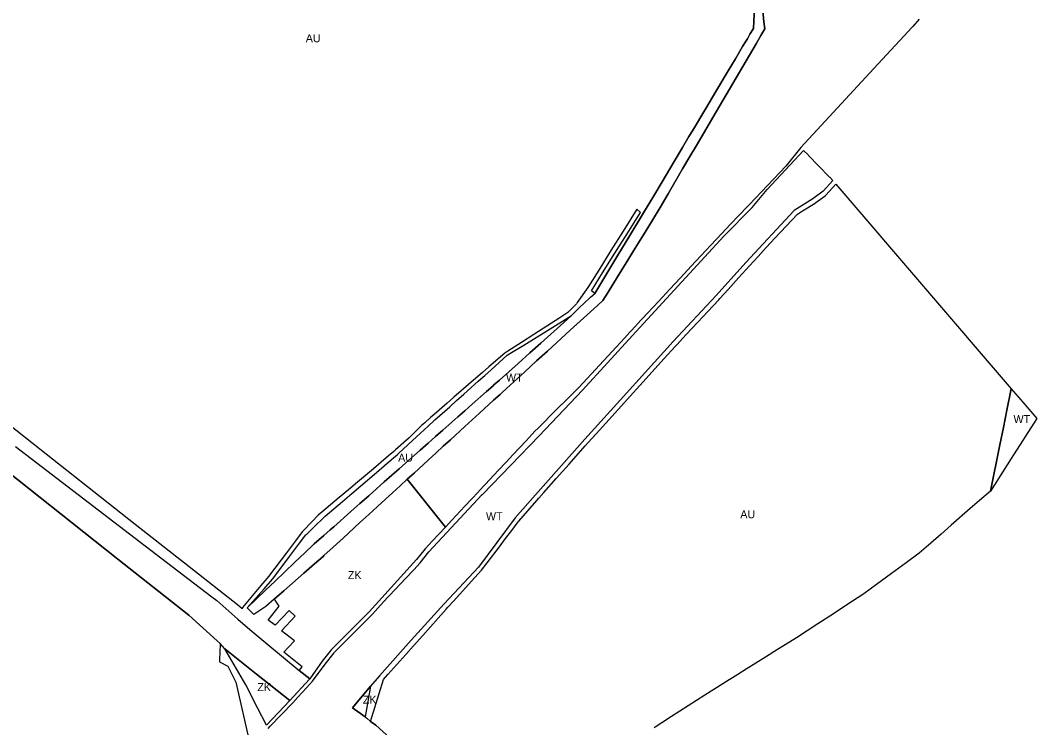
# Model space of a CAD drawing. Extents: x -537068 to -534056, y -1176840 to -1172401.
# Drawn here: x -534942 to -534307, y -1175088 to -1174646 of the extents above; entities that cross this region are included whole.
import ezdxf

# ---------------------------------------------------------------- set-up
doc = ezdxf.new("R2010")
doc.units = 0
for name, color, linetype in [('90640013', 7, 'Continuous'), ('90710013', 7, 'Continuous'), ('90750013', 7, 'Continuous')]:
    doc.layers.add(name, color=color, linetype=linetype)

msp = doc.modelspace()

# ---------------------------------------------------------------- linework, layer by layer
at = {"layer": '90640013'}
for points in [[(-534478.25, -1174635.29), (-534477.06, -1174647.13), (-534476.63, -1174651.47), (-534479.05, -1174655.6), (-534482.03, -1174660.69), (-534507.01, -1174703.32), (-534519.27, -1174724.24), (-534523.34, -1174731.19), (-534527.85, -1174738.88), (-534536.96, -1174754.44), (-534541.93, -1174762.92), (-534546.59, -1174770.87), (-534547.29, -1174772.07), (-534552.26, -1174780.1), (-534557.45, -1174788.49), (-534563.09, -1174797.6), (-534568.54, -1174806.41), (-534574.36, -1174815.82), (-534577.61, -1174821.08), (-534581.12, -1174824.28), (-534589.69, -1174832.1), (-534598.08, -1174839.75), (-534612.37, -1174852.78), (-534619.04, -1174858.87), (-534626.4, -1174865.59), (-534637.98, -1174876.15), (-534640.8, -1174878.72), (-534641.91, -1174879.74), (-534645.96, -1174883.45), (-534654.83, -1174891.57), (-534659.4, -1174895.76), (-534663.82, -1174899.8), (-534672.91, -1174908.12), (-534677.35, -1174912.19), (-534681.8, -1174916.26), (-534686.8, -1174920.84), (-534695.63, -1174928.92), (-534699.83, -1174932.76), (-534704.27, -1174936.83), (-534708.86, -1174941.03), (-534718.52, -1174949.88), (-534723.91, -1174954.82), (-534729.39, -1174959.83), (-534739.98, -1174969.53), (-534746.09, -1174975.13), (-534751.91, -1174980.46), (-534752.48, -1174980.98), (-534757.86, -1174985.68), (-534764.54, -1174991.52), (-534776.95, -1175002.38), (-534782.97, -1175007.65), (-534788.3, -1175012.3), (-534795.76, -1175017.23), (-534799.77, -1175013.15), (-534788.31, -1175002.15), (-534782.4, -1174996.48), (-534770.21, -1174984.78), (-534763.72, -1174978.55), (-534758.63, -1174973.67), (-534758, -1174973.12), (-534752.03, -1174967.91), (-534747.97, -1174964.37), (-534745.77, -1174962.42), (-534735.07, -1174952.95), (-534729.47, -1174947.99), (-534723.96, -1174943.11), (-534714.22, -1174934.48), (-534709.5, -1174930.3), (-534704.98, -1174926.3), (-534700.74, -1174922.54), (-534691.77, -1174914.6), (-534686.73, -1174910.14), (-534682.16, -1174906.09), (-534677.61, -1174902.06), (-534668.37, -1174893.88), (-534663.99, -1174890), (-534659.38, -1174885.92), (-534650.37, -1174877.94), (-534646.28, -1174874.32), (-534645.7, -1174873.81), (-534642.31, -1174870.78), (-534630.67, -1174860.39), (-534623.21, -1174853.72), (-534616.5, -1174847.72), (-534602.13, -1174834.89), (-534597.21, -1174830.49), (-534593.92, -1174827.17), (-534591.85, -1174825.08), (-534589.81, -1174823.19), (-534585.4, -1174819.11), (-534582.77, -1174816.67), (-534575.87, -1174805.3), (-534568.35, -1174792.9), (-534560.88, -1174780.59), (-534552.84, -1174767.33), (-534545.33, -1174754.73), (-534541.36, -1174748.06), (-534532.58, -1174733.33), (-534527.95, -1174725.55), (-534523.9, -1174718.75), (-534521.7, -1174715.06), (-534513.44, -1174701.2), (-534507.13, -1174690.61), (-534499.41, -1174677.64), (-534494.89, -1174670.06), (-534490.4, -1174662.53), (-534488.66, -1174659.61), (-534487.45, -1174657.59), (-534485.82, -1174654.85), (-534483.67, -1174651.23), (-534483.43, -1174646.62), (-534482.82, -1174635.13)], [(-534786.8, -1175088.49), (-534785.44, -1175087.07), (-534771.39, -1175072.42), (-534768.18, -1175068.9), (-534762.82, -1175063.03), (-534759.09, -1175058.95), (-534751.09, -1175048.36), (-534745.62, -1175041.13), (-534745.39, -1175040.83), (-534733.34, -1175028.8), (-534727.33, -1175022.8), (-534721.5, -1175016.99), (-534716.5, -1175011.48), (-534712.15, -1175006.68), (-534710.89, -1175005.34), (-534700.74, -1174994.57), (-534695.79, -1174989.31), (-534691.73, -1174984.99), (-534686.41, -1174978.09), (-534653.01, -1174942.33), (-534652.92, -1174942.24), (-534617.54, -1174905.69), (-534590.44, -1174877.09), (-534559.14, -1174842.98), (-534554.55, -1174837.98), (-534502.13, -1174780.9), (-534484.54, -1174763.09), (-534475.1, -1174751.76), (-534452.32, -1174727.32), (-534449.49, -1174730.22), (-534449.18, -1174730.55), (-534436.26, -1174743.82), (-534435.92, -1174744.17), (-534434.05, -1174746.09), (-534440.14, -1174752.91), (-534446.52, -1174757.52), (-534458.12, -1174764.98), (-534488.33, -1174797.34), (-534506.9, -1174817.91), (-534533.72, -1174846.67), (-534562.86, -1174878.98), (-534589.01, -1174907.71), (-534619.84, -1174942.57), (-534632.39, -1174956.93), (-534655.43, -1174987.67), (-534676.86, -1175010.7), (-534697.52, -1175033.38), (-534717.3, -1175055.5), (-534722.76, -1175062.11), (-534734.11, -1175075.61), (-534726.06, -1175081.25), (-534725.07, -1175082.09), (-534722.75, -1175084.04), (-534719.56, -1175086.43), (-534678.09, -1175123.81)], [(-534944.54, -1174912.26), (-534853.75, -1174981.84), (-534821.98, -1175006.14), (-534818.78, -1175008.59), (-534805.63, -1175020.1), (-534798.18, -1175026.62), (-534788.2, -1175034.87), (-534767.31, -1175052.15), (-534760.8, -1175057.54), (-534760.89, -1175057.67), (-534773.24, -1175070.91), (-534773.26, -1175070.93), (-534793.94, -1175054.45), (-534813.71, -1175038.69), (-534816.74, -1175035.44), (-534818.62, -1175033.74), (-534836.31, -1175017.73), (-534880.64, -1174982.65), (-534964.8, -1174916.06)]]:
    msp.add_lwpolyline(points, dxfattribs=at)
msp.add_lwpolyline([(-534335.66, -1174940.16), (-534329.75, -1174911.35), (-534327.52, -1174900.45), (-534325.32, -1174889.7), (-534322.58, -1174876.32), (-534315.41, -1174884.7), (-534306.74, -1174894.82), (-534322.65, -1174919.76)], close=True, dxfattribs=at)
at = {"layer": '90710013'}
for points in [[(-534760.8, -1175057.54), (-534767.31, -1175052.15), (-534765.58, -1175050.02), (-534776.91, -1175040.75), (-534774.24, -1175037.93), (-534770.39, -1175033.81), (-534778.49, -1175027.49), (-534769.81, -1175018.3), (-534773.59, -1175014.79), (-534782.29, -1175024), (-534786.84, -1175020.73), (-534779.83, -1175012.16), (-534782.3, -1175008.34), (-534782.97, -1175007.65), (-534776.95, -1175002.38), (-534764.54, -1174991.52), (-534757.86, -1174985.68), (-534752.48, -1174980.98), (-534751.91, -1174980.46), (-534746.09, -1174975.13), (-534739.98, -1174969.53), (-534729.39, -1174959.83), (-534723.91, -1174954.82), (-534718.52, -1174949.88), (-534708.86, -1174941.03), (-534704.27, -1174936.83), (-534699.83, -1174932.76), (-534676.03, -1174962.63), (-534680.11, -1174967.01), (-534684.1, -1174971.29), (-534688.65, -1174976.17), (-534694.19, -1174982.86), (-534723.62, -1175015.5), (-534747.13, -1175039.14), (-534752.93, -1175046.38)], [(-534773.26, -1175070.93), (-534787.72, -1175086.34), (-534787.86, -1175086.44), (-534793.42, -1175075.61), (-534800.74, -1175061.15), (-534813.71, -1175038.69), (-534793.94, -1175054.45)], [(-534726.06, -1175081.25), (-534734.11, -1175075.61), (-534722.76, -1175062.11)]]:
    msp.add_lwpolyline(points, close=True, dxfattribs=at)
at = {"layer": '90750013'}
for points in [[(-534482.82, -1174635.13), (-534483.43, -1174646.62), (-534483.67, -1174651.23), (-534485.82, -1174654.85), (-534487.45, -1174657.59), (-534488.66, -1174659.61), (-534490.4, -1174662.53), (-534494.89, -1174670.06), (-534499.41, -1174677.64), (-534507.13, -1174690.61), (-534513.44, -1174701.2), (-534521.7, -1174715.06), (-534523.9, -1174718.75), (-534527.95, -1174725.55), (-534532.58, -1174733.33), (-534541.36, -1174748.06), (-534545.33, -1174754.73), (-534552.84, -1174767.33), (-534560.88, -1174780.59), (-534568.35, -1174792.9), (-534575.87, -1174805.3), (-534582.77, -1174816.67), (-534584.75, -1174814.98), (-534577.84, -1174803.89), (-534570.19, -1174791.62), (-534562.58, -1174779.41), (-534554.28, -1174766.1), (-534556.56, -1174764.15), (-534565.02, -1174777.71), (-534572.63, -1174789.92), (-534580.26, -1174802.17), (-534587.03, -1174813.03), (-534593.65, -1174822.45), (-534594.13, -1174823.13), (-534595.88, -1174824.89), (-534599.49, -1174828.54), (-534604.65, -1174831.87), (-534620.87, -1174842.36), (-534628.44, -1174847.25), (-534636.95, -1174852.75), (-534638.95, -1174854.04), (-534648.87, -1174862.64), (-534652.89, -1174866.12), (-534656.99, -1174869.67), (-534666.1, -1174877.56), (-534670.72, -1174881.56), (-534674.99, -1174885.26), (-534681.63, -1174891.01), (-534684.36, -1174893.38), (-534685.1, -1174894.02), (-534688.97, -1174897.47), (-534690.89, -1174899.19), (-534693.48, -1174901.76), (-534698.23, -1174906.49), (-534698.64, -1174906.9), (-534707.2, -1174914.47), (-534708.32, -1174915.45), (-534711.49, -1174918.14), (-534716.11, -1174922.04), (-534721.01, -1174926.18), (-534730.87, -1174934.52), (-534736.54, -1174939.32), (-534742.3, -1174944.19), (-534753.14, -1174953.36), (-534755.41, -1174955.28), (-534759.21, -1174959.17), (-534764.81, -1174964.9), (-534765.49, -1174965.6), (-534769.74, -1174971.23), (-534775.34, -1174978.66), (-534785.92, -1174992.69), (-534786.4, -1174993.33), (-534791.25, -1174999.12), (-534802.78, -1175012.88), (-534802.96, -1175013.64), (-534805.96, -1175011.28), (-534836.01, -1174987.56), (-534869.76, -1174960.94), (-534938.24, -1174906.9), (-534950.35, -1174897.34)], [(-534380.19, -1174645.37), (-534384.14, -1174649.9), (-534384.9, -1174650.72), (-534387.03, -1174653.03), (-534408.37, -1174676.1), (-534454.07, -1174725.53), (-534463.51, -1174737.19), (-534486.32, -1174761.29), (-534487.23, -1174762.24), (-534493.01, -1174768.32), (-534498.14, -1174773.7), (-534503.37, -1174779.2), (-534510.2, -1174786.54), (-534516.46, -1174793.26), (-534522.47, -1174799.71), (-534529.2, -1174806.94), (-534535.79, -1174814.01), (-534542.79, -1174821.53), (-534549.73, -1174828.99), (-534556.43, -1174836.18), (-534556.76, -1174836.54), (-534560.85, -1174840.96), (-534564.27, -1174844.66), (-534571.86, -1174852.88), (-534579.89, -1174861.57), (-534592.47, -1174875.18), (-534593.35, -1174876.06), (-534599.87, -1174882.57), (-534606.77, -1174889.47), (-534618.12, -1174900.81), (-534620.16, -1174902.84), (-534621.84, -1174904.63), (-534625.7, -1174908.76), (-534633.94, -1174917.57), (-534638.3, -1174922.23), (-534642.84, -1174927.08), (-534651.23, -1174936.04), (-534655.2, -1174940.28), (-534655.44, -1174940.54), (-534659.79, -1174945.2), (-534663.93, -1174949.64), (-534672.06, -1174958.37), (-534676.03, -1174962.63), (-534699.83, -1174932.76), (-534695.63, -1174928.92), (-534686.8, -1174920.84), (-534681.8, -1174916.26), (-534677.35, -1174912.19), (-534672.91, -1174908.12), (-534663.82, -1174899.8), (-534659.4, -1174895.76), (-534654.83, -1174891.57), (-534645.96, -1174883.45), (-534641.91, -1174879.74), (-534640.8, -1174878.72), (-534637.98, -1174876.15), (-534626.4, -1174865.59), (-534619.04, -1174858.87), (-534612.37, -1174852.78), (-534598.08, -1174839.75), (-534589.69, -1174832.1), (-534581.12, -1174824.28), (-534577.61, -1174821.08), (-534574.36, -1174815.82), (-534568.54, -1174806.41), (-534563.09, -1174797.6), (-534557.45, -1174788.49), (-534552.26, -1174780.1), (-534547.29, -1174772.07), (-534546.59, -1174770.87), (-534541.93, -1174762.92), (-534536.96, -1174754.44), (-534527.85, -1174738.88), (-534523.34, -1174731.19), (-534519.27, -1174724.24), (-534507.01, -1174703.32), (-534482.03, -1174660.69), (-534479.05, -1174655.6), (-534476.63, -1174651.47), (-534477.06, -1174647.13), (-534478.25, -1174635.29)], [(-534678.09, -1175123.81), (-534719.56, -1175086.43), (-534722.75, -1175084.04), (-534714.69, -1175057.83), (-534713.41, -1175056.39), (-534711.9, -1175054.7), (-534706.46, -1175048.6), (-534700.74, -1175042.19), (-534695.91, -1175036.77), (-534690.19, -1175030.35), (-534680.57, -1175019.56), (-534675.58, -1175013.96), (-534674.52, -1175012.78), (-534670.85, -1175008.75), (-534661.59, -1174998.56), (-534657.59, -1174994.15), (-534653.5, -1174989.66), (-534649.98, -1174985.02), (-534642.34, -1174974.97), (-534638.47, -1174969.88), (-534634.53, -1174964.69), (-534631.12, -1174960.2), (-534630.19, -1174958.97), (-534623.14, -1174950.91), (-534618.91, -1174946.08), (-534617.59, -1174944.56), (-534614.56, -1174941.14), (-534606.8, -1174932.37), (-534602.87, -1174927.92), (-534598.76, -1174923.27), (-534588.66, -1174911.85), (-534586.79, -1174909.73), (-534581.98, -1174904.44), (-534575.89, -1174897.74), (-534562.26, -1174882.76), (-534560.64, -1174880.98), (-534554.5, -1174874.18), (-534546.87, -1174865.73), (-534539.53, -1174857.59), (-534532.32, -1174849.59), (-534531.53, -1174848.72), (-534525.62, -1174842.38), (-534518.45, -1174834.69), (-534512.17, -1174827.96), (-534505.32, -1174820.62), (-534504.67, -1174819.92), (-534499.52, -1174814.21), (-534492.97, -1174806.95), (-534486.14, -1174799.39), (-534480.75, -1174793.58), (-534475.68, -1174788.11), (-534470.07, -1174782.05), (-534456.21, -1174767.1), (-534452.95, -1174765.07), (-534445.17, -1174760.23), (-534444.75, -1174759.97), (-534438.8, -1174755.67), (-534438.37, -1174755.36), (-534432.09, -1174748.37), (-534430.84, -1174749.83), (-534322.58, -1174876.32), (-534325.32, -1174889.7), (-534327.52, -1174900.45), (-534329.75, -1174911.35), (-534335.66, -1174940.16), (-534342.43, -1174946.08), (-534348.23, -1174951.15), (-534360.12, -1174961.55), (-534366.45, -1174967.08), (-534372.88, -1174972.7), (-534380.03, -1174978.95), (-534388.21, -1174984.95), (-534397.41, -1174991.7), (-534406.77, -1174998.56), (-534414.65, -1175004.34), (-534415.29, -1175004.76), (-534424.62, -1175010.84), (-534433.73, -1175016.78), (-534443.35, -1175023.05), (-534456.75, -1175031.78), (-534461.18, -1175034.54), (-534468.52, -1175039.11), (-534476.13, -1175043.85), (-534488.09, -1175051.31), (-534493.49, -1175054.67), (-534498.46, -1175057.77), (-534498.84, -1175058.01), (-534508.28, -1175064.03), (-534514.04, -1175067.71), (-534519.23, -1175071.02), (-534529.59, -1175077.63), (-534534.82, -1175080.97), (-534540.88, -1175084.84), (-534545.11, -1175087.54), (-534545.66, -1175087.96)], [(-534964.8, -1174916.06), (-534880.64, -1174982.65), (-534836.31, -1175017.73), (-534818.62, -1175033.74), (-534816.74, -1175035.44), (-534816.98, -1175041.13), (-534817.15, -1175045), (-534817.23, -1175046.88), (-534811.97, -1175049.46), (-534810.08, -1175053.22), (-534806.93, -1175059.47), (-534798.45, -1175096.97)]]:
    msp.add_lwpolyline(points, dxfattribs=at)
msp.add_lwpolyline([(-534799.77, -1175013.15), (-534789.27, -1175001.16), (-534784, -1174995.14), (-534783.84, -1174994.93), (-534773.36, -1174981.02), (-534767.78, -1174973.61), (-534763.21, -1174967.54), (-534762.89, -1174967.22), (-534757.18, -1174961.64), (-534752.89, -1174957.43), (-534751.08, -1174955.89), (-534740.27, -1174946.65), (-534734.55, -1174941.76), (-534728.92, -1174936.95), (-534719.08, -1174928.54), (-534714.23, -1174924.39), (-534709.63, -1174920.47), (-534706.04, -1174917.4), (-534705.36, -1174916.77), (-534696.53, -1174908.62), (-534691.61, -1174904.08), (-534687.06, -1174899.88), (-534682.82, -1174895.96), (-534682.55, -1174895.71), (-534673.31, -1174887.44), (-534669.06, -1174883.64), (-534664.5, -1174879.56), (-534655.51, -1174871.52), (-534651.46, -1174867.9), (-534647.49, -1174864.35), (-534637.43, -1174855.34), (-534635.7, -1174854.27), (-534627.07, -1174848.94), (-534619.38, -1174844.19), (-534602.88, -1174833.99), (-534597.21, -1174830.49), (-534602.13, -1174834.89), (-534616.5, -1174847.72), (-534623.21, -1174853.72), (-534630.67, -1174860.39), (-534642.31, -1174870.78), (-534645.7, -1174873.81), (-534646.28, -1174874.32), (-534650.37, -1174877.94), (-534659.38, -1174885.92), (-534663.99, -1174890), (-534668.37, -1174893.88), (-534677.61, -1174902.06), (-534682.16, -1174906.09), (-534686.73, -1174910.14), (-534691.77, -1174914.6), (-534700.74, -1174922.54), (-534704.98, -1174926.3), (-534709.5, -1174930.3), (-534714.22, -1174934.48), (-534723.96, -1174943.11), (-534729.47, -1174947.99), (-534735.07, -1174952.95), (-534745.77, -1174962.42), (-534747.97, -1174964.37), (-534752.03, -1174967.91), (-534758, -1174973.12), (-534758.63, -1174973.67), (-534763.72, -1174978.55), (-534770.21, -1174984.78), (-534782.4, -1174996.48), (-534788.31, -1175002.15)], close=True, dxfattribs=at)

# ---------------------------------------------------------------- texts
at = {"layer": '90640013'}
for rotation, p in [(360, (-534638.2, -1174871.73)), (360, (-534321.2, -1174897.71)), (0, (-534650.71, -1174958.35))]:
    msp.add_text('WT', height=5, rotation=rotation, dxfattribs=at).set_placement(p)
at = {"layer": '90710013'}
for rotation, p in [(360, (-534736.98, -1174995.15)), (0, (-534793.49, -1175065.15)), (0, (-534727.64, -1175072.99))]:
    msp.add_text('ZK', height=5, rotation=rotation, dxfattribs=at).set_placement(p)
at = {"layer": '90750013'}
for rotation, p in [(360, (-534763.26, -1174659.8)), (360, (-534705.57, -1174921.82)), (0, (-534491.86, -1174957.17))]:
    msp.add_text('AU', height=5, rotation=rotation, dxfattribs=at).set_placement(p)

doc.saveas('drawing.dxf')
